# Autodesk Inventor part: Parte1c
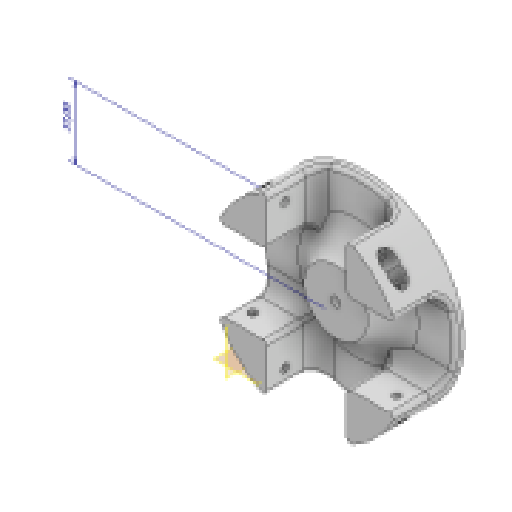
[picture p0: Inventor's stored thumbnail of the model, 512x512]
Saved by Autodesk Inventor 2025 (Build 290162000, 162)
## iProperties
Created: 2025-05
Part Number: Parte1c
Material: Generico
Document SubType Name: Modeling
Designer: R5800u
Density: 1 g/cm^3
Appearance: Default
Author: R5800u
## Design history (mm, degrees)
node "Annotazioni"
  node "Quota lineare 1" dims "d0" = 100, "d1" = 45 deg, "d3" = 25, "d8" = 6, "d9" = 6, "d10" = 3, "d11" = 3, "d22" = 6, "d23" = 6, "d45" = 37 (derived)
sketch "Schizzo1" dims "d0" = 100
  geometry: L1 (0, 0)-(35.355, 35.355); L2 (0, 0)-(50, 0); L3 (20.572, 20.572)-(20.572, 45.572); L4 (20.572, 20.572)-(45.572, 20.572); L5 (0, 0)-(0, 44.829) reference; L6 (-20.572, 20.572)-(-20.572, 45.572); L7 (0, 0)-(-35.355, 35.355); L8 (-20.572, 20.572)-(-45.572, 20.572); L9 (0, 0)-(56.569, 0); L10 (26.572, 42.355)-(26.572, 26.572); L11 (26.572, 26.572)-(42.355, 26.572); L12 (-26.572, 42.355)-(-26.572, 26.572); L13 (-26.572, 26.572)-(-42.355, 26.572); L14 (-20.572, 24.815)-(0, 4.243); L15 (0, 4.243)-(20.572, 24.815); L16 (24.815, 20.572)-(0, -4.243); L17 (0, -4.243)-(-24.815, 20.572); L18 (20.572, -20.572)-(20.572, -45.572); L19 (0, -4.243)-(20.572, -24.815); L20 (26.572, -42.355)-(26.572, -26.572); L21 (24.815, -20.572)-(0, 4.243); L22 (0, 0)-(35.355, -35.355); L23 (26.572, -26.572)-(42.355, -26.572); L24 (20.572, -20.572)-(45.572, -20.572); L25 (0, 0)-(0, -44.829); L26 (-20.572, -24.815)-(0, -4.243); L27 (0, 4.243)-(-24.815, -20.572); L28 (0, 0)-(-35.355, -35.355); L29 (-20.572, -20.572)-(-20.572, -45.572); L30 (-26.572, -42.355)-(-26.572, -26.572); L31 (-26.572, -26.572)-(-42.355, -26.572); L32 (-20.572, -20.572)-(-45.572, -20.572); 3 further points
  constraints: 64 end point, 25 symmetric about line, 13 point on line, 3 vertical, 2 coincident, 2 horizontal, 1 equal length, 9 other
  dimensions: "d1" = 45 deg angle of L2 L1; "d3" = 25 distance of L3.start L4.end; "d8" = 6 distance between parallel lines of L3 L10; "d9" = 6 distance between parallel lines of L6 L12; "d10" = 3 distance between parallel lines of L7 L14; "d11" = 3 distance between parallel lines of L1 L16; "d22" = 6 distance between parallel lines of L4 L11; "d23" = 6 distance between parallel lines of L8 L13
extrude "Estrusione1" new body sketch "Schizzo1" stored distance "d4" = 75; taper "d5" = 0 deg
node "Piano di lavoro1"
sketch "Schizzo3" dims "d24" = 100
  geometry: L1 (0, 0)-(35.355, 35.355); L2 (0, 0)-(50, 0); L3 (20.572, 20.572)-(20.572, 45.572); L4 (20.572, 20.572)-(45.572, 20.572); L5 (0, 0)-(0, 44.829); L6 (-20.572, 20.572)-(-20.572, 45.572); L7 (0, 0)-(-35.355, 35.355); L8 (-20.572, 20.572)-(-45.572, 20.572); L9 (0, 0)-(56.569, 0); L10 (26.572, 42.355)-(26.572, 26.572); L11 (26.572, 26.572)-(42.355, 26.572); L12 (-26.572, 42.355)-(-26.572, 26.572); L13 (-26.572, 26.572)-(-42.355, 26.572); L14 (-20.572, 24.815)-(0, 4.243); L15 (0, 4.243)-(20.572, 24.815); L16 (24.815, 20.572)-(0, -4.243); L17 (0, -4.243)-(-24.815, 20.572); L18 (20.572, -20.572)-(20.572, -45.572); L19 (0, -4.243)-(20.572, -24.815); L20 (26.572, -42.355)-(26.572, -26.572); L21 (24.815, -20.572)-(0, 4.243); L22 (0, 0)-(35.355, -35.355); L23 (26.572, -26.572)-(42.355, -26.572); L24 (20.572, -20.572)-(45.572, -20.572); L25 (0, 0)-(0, -44.829); L26 (-20.572, -24.815)-(0, -4.243); L27 (0, 4.243)-(-24.815, -20.572); L28 (0, 0)-(-35.355, -35.355); L29 (-20.572, -20.572)-(-20.572, -45.572); L30 (-26.572, -42.355)-(-26.572, -26.572); L31 (-26.572, -26.572)-(-42.355, -26.572); L32 (-20.572, -20.572)-(-45.572, -20.572); 16 further points
  constraints: 64 end point, 25 symmetric about line, 13 point on line, 2 coincident, 2 horizontal, 2 parallel, 2 vertical, 1 equal length, 9 other
  dimensions: "d25" = 45 deg angle of L2 L1; "d26" = 25 distance of L3.start L4.end; "d27" = 6 distance between parallel lines of L3 L10; "d28" = 6 distance between parallel lines of L6 L12; "d29" = 3 distance between parallel lines of L7 L14; "d30" = 3 distance between parallel lines of L1 L16; "d31" = 6 distance between parallel lines of L4 L11; "d32" = 6 distance between parallel lines of L8 L13; "d41" = 3 distance between parallel lines of L1 L15; "d42" = 3 distance between parallel lines of L7 L17; "d63" = 25 distance of L18.start L24.end (derived); "d64" = 25 distance of L18.start L18.end (derived); "d65" = 41.14378 distance between parallel lines of L32 L8 (derived); "d66" = 41.14378 distance between parallel lines of L24 L4 (derived); "d67" = 41.14378 distance between parallel lines of L3 L6 (derived); "d68" = 41.14378 distance between parallel lines of L18 L29 (derived)
extrude "Estrusione4" cut sketch "Schizzo3" extent not by distance; stored distance "d33" = 30; taper "d34" = 0 deg
sketch "Schizzo4"
  geometry: L1 (45.572, 37.5)-(45.572, 3) reference; L2 (45.572, 20.25)-(0, 20.25); L3 (0, 3)-(0, 37.5) reference; C1 r 2 at (37, 20.25); 2 further points
  constraints: 2 end point, 2 midpoint, 1 centre point, 1 coincident, 1 point on line
  dimensions: "d36" = 37 horizontal distance of point (0, 0) point (37, 20.25); "d37" = 4 diameter of C1
extrude "Estrusione5" cut sketch "Schizzo4" extent not by distance; stored distance "d38" = 0; taper "d39" = 0 deg
pattern_circular "Serie circolare1" dims angle "d47" = 360 deg
sketch "Schizzo5"
  geometry: C1 r 50 at (0, 0) reference; 1 further point
extrude "Estrusione6" cut sketch "Schizzo5" distance "d53" = 36; taper "d54" = 0 deg
sketch "Schizzo6"
  geometry: L1 (45.572, -20.572)-(20.572, -20.572) reference; L2 (20.572, 20.572)-(45.572, 20.572) reference; L3 (20.572, 45.572)-(20.572, 20.572) reference; L4 (-20.572, 20.572)-(-20.572, 45.572) reference; L5 (-45.572, 20.572)-(-20.572, 20.572) reference; L6 (-20.572, -20.572)-(-45.572, -20.572) reference; L7 (-20.572, -45.572)-(-20.572, -20.572) reference; L8 (20.572, -20.572)-(20.572, -45.572) reference; L9 (-20.572, 24.815)-(-24.815, 20.572); L10 (-24.815, 20.572)-(-20.572, 24.815); L11 (-24.815, -20.572)-(-20.572, -24.815); L12 (20.572, 24.815)-(24.815, 20.572); L13 (24.815, -20.572)-(20.572, -24.815); C1 r 16 at (0, 0); A1 r 50 centre (0, 0) between (45.572, 20.572) and (20.572, 45.572) reference; A2 r 50 centre (0, 0) between (-20.572, 45.572) and (-45.572, 20.572) reference; A3 r 50 centre (0, 0) between (-45.572, -20.572) and (-20.572, -45.572) reference; A4 r 50 centre (0, 0) between (20.572, -45.572) and (45.572, -20.572) reference; A5 r 35 centre (0, 53.131) between (-20.572, 24.815) and (20.572, 24.815); A6 r 35 centre (-53.131, 0) between (-24.815, -20.572) and (-24.815, 20.572); A7 r 35 centre (0, -53.131) between (20.572, -24.815) and (-20.572, -24.815); A8 r 35 centre (53.131, 0) between (24.815, 20.572) and (24.815, -20.572); 1 further point
  constraints: 10 end point, 8 point on circle, 5 centre point, 1 coincident, 1 parallel, 1 perpendicular, 17 other
  dimensions: "d55" = 32 diameter of C1; "d109" = 35 radius of A5; "d112" = 360 deg dimension on point (0, 0) A5.centre (derived)
extrude "Estrusione7" join sketch "Schizzo6" stored distance "d56" = 36; taper "d57" = 0 deg
sketch "Schizzo7"
  geometry: C1 r 2.5 at (0, 0); 1 further point
  constraints: 1 centre point, 1 coincident
  dimensions: "d69" = 5 diameter of C1
extrude "Estrusione8" cut sketch "Schizzo7" extent not by distance; stored distance "d70" = 10; taper "d71" = 0 deg
sketch "Schizzo8"
  geometry: L1 (20.572, 20.572)-(45.572, 20.572) reference; L2 (20.572, 45.572)-(20.572, 20.572) reference; L3 (-20.572, 20.572)-(-20.572, 45.572) reference; L4 (-45.572, 20.572)-(-20.572, 20.572) reference; L5 (-20.572, -20.572)-(-45.572, -20.572) reference; L6 (-20.572, -45.572)-(-20.572, -20.572) reference; L7 (20.572, -20.572)-(20.572, -45.572) reference; L8 (45.572, -20.572)-(20.572, -20.572) reference; A1 r 50 centre (0, 0) between (45.572, 20.572) and (20.572, 45.572) reference; A2 r 50 centre (0, 0) between (20.572, -45.572) and (45.572, -20.572) reference; A3 r 50 centre (0, 0) between (-45.572, -20.572) and (-20.572, -45.572) reference; A4 r 50 centre (0, 0) between (-20.572, 45.572) and (-45.572, 20.572) reference; A5 r 35 centre (0, 53.131) between (-20.572, 24.815) and (20.572, 24.815); A6 r 35 centre (-53.131, 0) between (-24.815, -20.572) and (-24.815, 20.572); A7 r 35 centre (0, -53.131) between (20.572, -24.815) and (-20.572, -24.815); A8 r 35 centre (53.131, 0) between (24.815, 20.572) and (24.815, -20.572); 9 further points
  constraints: 8 point on circle, 4 centre point, 17 other
  dimensions: "d104" = 35 radius of A5; "d107" = 360 deg dimension on point (0, 0) A5.centre (derived)
extrude "Estrusione9" cut sketch "Schizzo8" distance "d72" = 8; taper "d73" = 0 deg
node "Piano di lavoro3"
sketch "Schizzo10"
  geometry: C1 r 2 at (-17.25, 8.572) reference; C2 r 4 at (-17.25, 8.572); 1 further point
  constraints: 1 centre point, 1 coincident
  dimensions: "d86" = 8 diameter of C2
extrude "Estrusione11" cut sketch "Schizzo10" distance "d87" = 13; taper "d88" = 0 deg
node "Piano di lavoro4"
sketch "Schizzo11"
  geometry: C1 r 2 at (8.572, -17.25) reference; C2 r 4 at (8.572, -17.25); 1 further point
  constraints: 1 centre point, 1 coincident
  dimensions: "d90" = 8 diameter of C2
extrude "Estrusione12" cut sketch "Schizzo11" distance "d91" = 13; taper "d92" = 0 deg
pattern_circular "Serie circolare4" dims "d94" = 360 deg
fillet "Raccordo21" dims "d124" = 6
fillet "Raccordo22" dims "d125" = 8
fillet "Raccordo23" dims "d126" = 2
fillet "Raccordo24" dims "d127" = 15
sketch "Schizzo12"
  geometry: C1 r 2.5 at (0, 0) reference; C2 r 6 at (0, 0); 1 further point
  constraints: 1 centre point, 1 coincident
  dimensions: "d128" = 12 diameter of C2
extrude "Estrusione13" cut sketch "Schizzo12" distance "d129" = 13; taper "d130" = 0 deg
sketch "Schizzo14"
  geometry: C1 r 6 at (0, 0) reference; C2 r 16 at (0, 0) reference; C3 r 2.5 at (0, 0) reference; C4 r 20 at (0, 0); 1 further point
  constraints: 1 centre point, 1 coincident
  dimensions: "d133" = 40 diameter of C4
extrude "Estrusione14" cut sketch "Schizzo14" distance "d131" = 15; taper "d132" = 0 deg
fillet "Raccordo25" dims "d134" = 2
sketch "Schizzo15"
  geometry: C1 r 1.6 at (-7.071, -7.071) reference; C2 r 1.6 at (9.659, -2.588) reference; C3 r 1.6 at (-2.588, 9.659) reference; 1 further point
hole "Foro1" sketch "Schizzo15" at (9.659, -2.588), (-7.071, -7.071), (-2.588, 9.659) diameter "d135" = 3.2; stored, may be unused: countersink angle "d139" = 90 deg, drill point angle "d141" = 118 deg; dims "d136" = 6, "d137" = 6.3, "d138" = 2, "d140" = 8
sketch "Schizzo16" dims "d142" = 6.5
  geometry: L1 (-3.821, -7.071)-(-5.446, -9.886); L2 (-5.446, -9.886)-(-8.696, -9.886); L3 (-8.696, -9.886)-(-10.321, -7.071); L4 (-10.321, -7.071)-(-8.696, -4.256); L5 (-8.696, -4.256)-(-5.446, -4.256); L6 (-5.446, -4.256)-(-3.821, -7.071); C1 r 1.6 at (-7.071, -7.071) reference; 3 further points
  constraints: 12 end point, 2 coincident, 1 horizontal alignment, 15 other
extrude "Estrusione15" cut sketch "Schizzo16" distance "d143" = 5; taper "d144" = 0 deg
pattern_circular "Serie circolare8" dims angle "d146" = 360 deg
fillet "Raccordo26" dims "d148" = 2
node "Solido1"
node "Linea chiusa proiettata1"
node "Schizzo - Serie circolare1" dims "d107" = 360 deg (derived)
node "Linea chiusa proiettata2"
node "Schizzo - Serie circolare2" dims "d112" = 360 deg (derived)
node "Linea chiusa proiettata3"
node "Riferimento4"
node "Riferimento5"
node "Riferimento6"
other parameters: "d12" = 3, "d18" = 2, "d19" = 2, "d43" = -3.54436 (derived), "d44" = -20.19224 (derived)
